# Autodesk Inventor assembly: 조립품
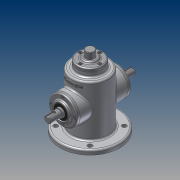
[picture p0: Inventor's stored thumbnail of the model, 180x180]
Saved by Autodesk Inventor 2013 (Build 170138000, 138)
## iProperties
Created: 2014-12
Part Number: 조립품
Document SubType Name: Assembly
Designer: CAD-B27
Author: CAD-B27
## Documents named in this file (12)
- C:\Users\CAD-B27\Documents\441228V1006\조립품.iam
- C:\Users\CAD-B27\Documents\441228V1006\본체.ipt
- C:\Users\CAD-B27\Documents\441228V1006\M3x0.5x8.ipt
- M3x0.5.ipt
- C:\Users\CAD-B27\Documents\441228V1006\베어링 6002.ipt
- 베어링 6002.ipt
- C:\Users\CAD-B27\Documents\441228V1006\상단커버.ipt
- C:\Users\CAD-B27\Documents\441228V1006\슬라이드.ipt
- C:\Users\CAD-B27\Documents\441228V1006\오일실.ipt
- 오일실.ipt
- C:\Users\CAD-B27\Documents\441228V1006\축.ipt
- C:\Users\CAD-B27\Documents\441228V1006\커버.ipt
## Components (12 placed, 1 different names)
1. M3x0.5:2 — 각도:1
2. M3x0.5:4
3. M3x0.5:5
4. M3x0.5:6
5. M3x0.5:1 — 각도:2
6. M3x0.5:7
7. M3x0.5:8
8. M3x0.5:9
9. M3x0.5:3 — 각도:3
10. M3x0.5:10
11. M3x0.5:11
12. M3x0.5:12
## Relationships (3: Angle 3)
- 각도:1 [Angle]: M3x0.5:2
- 각도:2 [Angle]: M3x0.5:1
- 각도:3 [Angle]: M3x0.5:3
